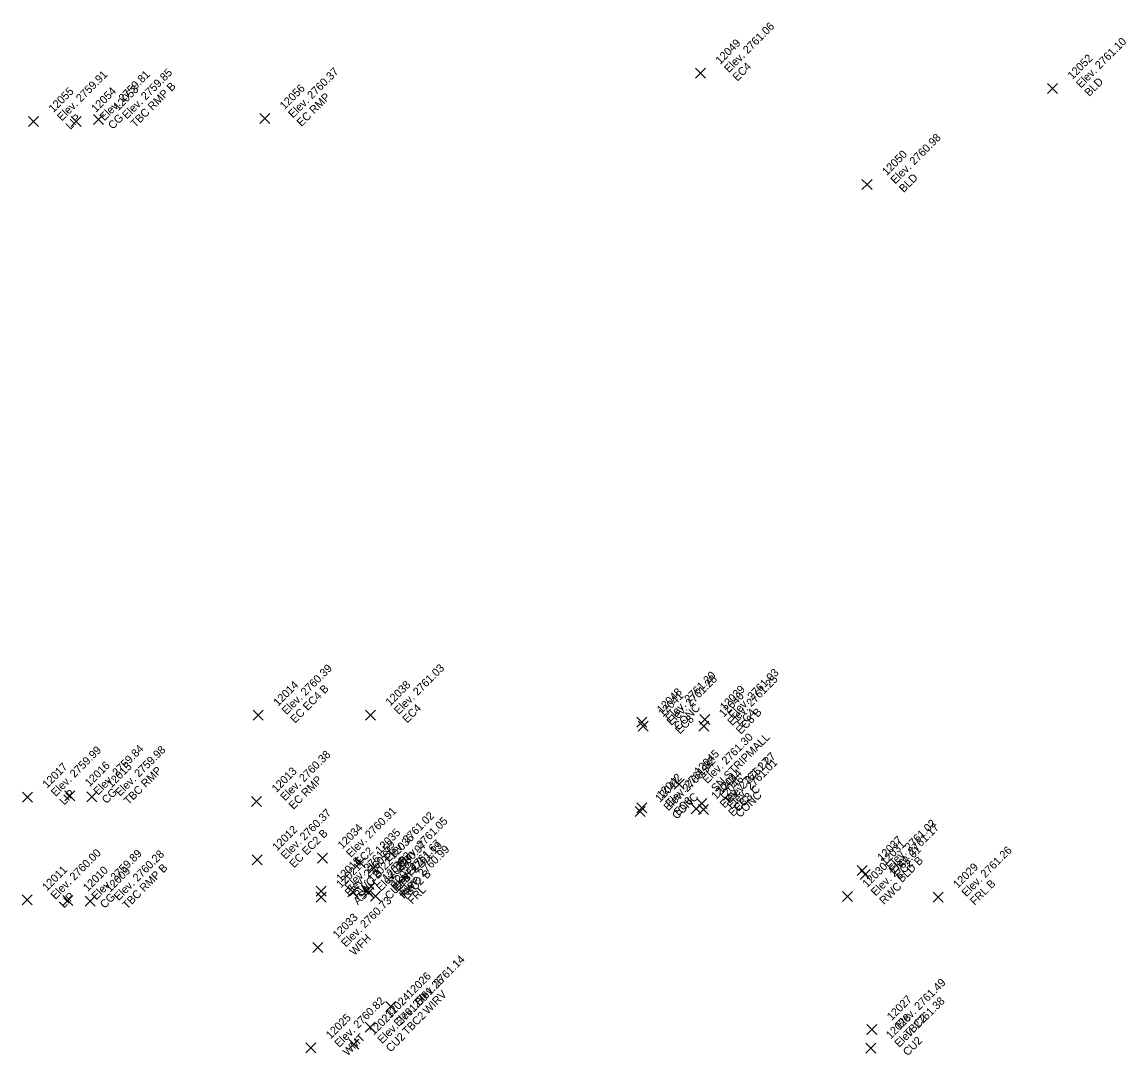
# Model space of a CAD drawing. Extents: x 2493999 to 2503109, y 700767 to 706646.
# Drawn here: x 2502310.86 to 2502343.96, y 702162.62 to 702193.6 of the extents above; entities that cross this region are included whole.
import ezdxf

# ---------------------------------------------------------------- set-up
doc = ezdxf.new("R2010")
doc.units = 0
doc.layers.add('ALG_CL_BLUE_Horiz', color=7, linetype='Continuous')
doc.layers.add('DES_SURFACE_Existing-Ground', color=7, linetype='Continuous')

msp = doc.modelspace()

# ---------------------------------------------------------------- linework, layer by layer
at = {"layer": 'ALG_CL_BLUE_Horiz'}
for points in [[(2502331.202, 702192.065), (2502331.052, 702192.215), (2502331.202, 702192.065), (2502331.052, 702191.915), (2502331.202, 702192.065), (2502331.352, 702191.915), (2502331.202, 702192.065), (2502331.352, 702192.215)], [(2502341.758, 702191.608), (2502341.608, 702191.758), (2502341.758, 702191.608), (2502341.608, 702191.458), (2502341.758, 702191.608), (2502341.908, 702191.458), (2502341.758, 702191.608), (2502341.908, 702191.758)], [(2502311.202, 702190.617), (2502311.052, 702190.767), (2502311.202, 702190.617), (2502311.052, 702190.467), (2502311.202, 702190.617), (2502311.352, 702190.467), (2502311.202, 702190.617), (2502311.352, 702190.767)], [(2502312.478, 702190.622), (2502312.328, 702190.772), (2502312.478, 702190.622), (2502312.328, 702190.472), (2502312.478, 702190.622), (2502312.628, 702190.472), (2502312.478, 702190.622), (2502312.628, 702190.772)], [(2502313.149, 702190.676), (2502312.999, 702190.826), (2502313.149, 702190.676), (2502312.999, 702190.526), (2502313.149, 702190.676), (2502313.299, 702190.526), (2502313.149, 702190.676), (2502313.299, 702190.826)], [(2502318.135, 702190.706), (2502317.985, 702190.856), (2502318.135, 702190.706), (2502317.985, 702190.556), (2502318.135, 702190.706), (2502318.285, 702190.556), (2502318.135, 702190.706), (2502318.285, 702190.856)], [(2502336.196, 702188.728), (2502336.046, 702188.878), (2502336.196, 702188.728), (2502336.046, 702188.578), (2502336.196, 702188.728), (2502336.346, 702188.578), (2502336.196, 702188.728), (2502336.346, 702188.878)], [(2502317.94, 702172.81), (2502317.79, 702172.96), (2502317.94, 702172.81), (2502317.79, 702172.66), (2502317.94, 702172.81), (2502318.09, 702172.66), (2502317.94, 702172.81), (2502318.09, 702172.96)], [(2502321.305, 702172.818), (2502321.155, 702172.968), (2502321.305, 702172.818), (2502321.155, 702172.668), (2502321.305, 702172.818), (2502321.455, 702172.668), (2502321.305, 702172.818), (2502321.455, 702172.968)], [(2502331.334, 702172.68), (2502331.184, 702172.83), (2502331.334, 702172.68), (2502331.184, 702172.53), (2502331.334, 702172.68), (2502331.484, 702172.53), (2502331.334, 702172.68), (2502331.484, 702172.83)], [(2502329.443, 702172.6), (2502329.293, 702172.75), (2502329.443, 702172.6), (2502329.293, 702172.45), (2502329.443, 702172.6), (2502329.593, 702172.45), (2502329.443, 702172.6), (2502329.593, 702172.75)], [(2502329.483, 702172.487), (2502329.333, 702172.637), (2502329.483, 702172.487), (2502329.333, 702172.337), (2502329.483, 702172.487), (2502329.633, 702172.337), (2502329.483, 702172.487), (2502329.633, 702172.637)], [(2502331.304, 702172.484), (2502331.154, 702172.634), (2502331.304, 702172.484), (2502331.154, 702172.334), (2502331.304, 702172.484), (2502331.454, 702172.334), (2502331.304, 702172.484), (2502331.454, 702172.634)], [(2502330.561, 702170.747), (2502330.411, 702170.897), (2502330.561, 702170.747), (2502330.411, 702170.597), (2502330.561, 702170.747), (2502330.711, 702170.597), (2502330.561, 702170.747), (2502330.711, 702170.897)], [(2502311.017, 702170.355), (2502310.867, 702170.505), (2502311.017, 702170.355), (2502310.867, 702170.205), (2502311.017, 702170.355), (2502311.167, 702170.205), (2502311.017, 702170.355), (2502311.167, 702170.505)], [(2502312.289, 702170.397), (2502312.139, 702170.547), (2502312.289, 702170.397), (2502312.139, 702170.247), (2502312.289, 702170.397), (2502312.439, 702170.247), (2502312.289, 702170.397), (2502312.439, 702170.547)], [(2502312.947, 702170.365), (2502312.797, 702170.515), (2502312.947, 702170.365), (2502312.797, 702170.215), (2502312.947, 702170.365), (2502313.097, 702170.215), (2502312.947, 702170.365), (2502313.097, 702170.515)], [(2502317.892, 702170.226), (2502317.742, 702170.376), (2502317.892, 702170.226), (2502317.742, 702170.076), (2502317.892, 702170.226), (2502318.042, 702170.076), (2502317.892, 702170.226), (2502318.042, 702170.376)], [(2502329.439, 702170.037), (2502329.289, 702170.187), (2502329.439, 702170.037), (2502329.289, 702169.887), (2502329.439, 702170.037), (2502329.589, 702169.887), (2502329.439, 702170.037), (2502329.589, 702170.187)], [(2502331.243, 702170.166), (2502331.093, 702170.316), (2502331.243, 702170.166), (2502331.093, 702170.016), (2502331.243, 702170.166), (2502331.393, 702170.016), (2502331.243, 702170.166), (2502331.393, 702170.316)], [(2502329.39, 702169.93), (2502329.24, 702170.08), (2502329.39, 702169.93), (2502329.24, 702169.78), (2502329.39, 702169.93), (2502329.54, 702169.78), (2502329.39, 702169.93), (2502329.54, 702170.08)], [(2502331.076, 702170.009), (2502330.926, 702170.159), (2502331.076, 702170.009), (2502330.926, 702169.859), (2502331.076, 702170.009), (2502331.226, 702169.859), (2502331.076, 702170.009), (2502331.226, 702170.159)], [(2502331.29, 702169.981), (2502331.14, 702170.131), (2502331.29, 702169.981), (2502331.14, 702169.831), (2502331.29, 702169.981), (2502331.44, 702169.831), (2502331.29, 702169.981), (2502331.44, 702170.131)], [(2502317.911, 702168.472), (2502317.761, 702168.622), (2502317.911, 702168.472), (2502317.761, 702168.322), (2502317.911, 702168.472), (2502318.061, 702168.322), (2502317.911, 702168.472), (2502318.061, 702168.622)], [(2502319.87, 702168.529), (2502319.72, 702168.679), (2502319.87, 702168.529), (2502319.72, 702168.379), (2502319.87, 702168.529), (2502320.02, 702168.379), (2502319.87, 702168.529), (2502320.02, 702168.679)], [(2502321.001, 702168.387), (2502320.851, 702168.537), (2502321.001, 702168.387), (2502320.851, 702168.237), (2502321.001, 702168.387), (2502321.151, 702168.237), (2502321.001, 702168.387), (2502321.151, 702168.537)], [(2502321.407, 702168.23), (2502321.257, 702168.38), (2502321.407, 702168.23), (2502321.257, 702168.08), (2502321.407, 702168.23), (2502321.557, 702168.08), (2502321.407, 702168.23), (2502321.557, 702168.38)], [(2502336.054, 702168.16), (2502335.904, 702168.31), (2502336.054, 702168.16), (2502335.904, 702168.01), (2502336.054, 702168.16), (2502336.204, 702168.01), (2502336.054, 702168.16), (2502336.204, 702168.31)], [(2502336.142, 702168.034), (2502335.992, 702168.184), (2502336.142, 702168.034), (2502335.992, 702167.884), (2502336.142, 702168.034), (2502336.292, 702167.884), (2502336.142, 702168.034), (2502336.292, 702168.184)], [(2502319.825, 702167.538), (2502319.675, 702167.688), (2502319.825, 702167.538), (2502319.675, 702167.388), (2502319.825, 702167.538), (2502319.975, 702167.388), (2502319.825, 702167.538), (2502319.975, 702167.688)], [(2502320.775, 702167.518), (2502320.625, 702167.668), (2502320.775, 702167.518), (2502320.625, 702167.368), (2502320.775, 702167.518), (2502320.925, 702167.368), (2502320.775, 702167.518), (2502320.925, 702167.668)], [(2502321.205, 702167.552), (2502321.055, 702167.702), (2502321.205, 702167.552), (2502321.055, 702167.402), (2502321.205, 702167.552), (2502321.355, 702167.402), (2502321.205, 702167.552), (2502321.355, 702167.702)], [(2502321.245, 702167.498), (2502321.095, 702167.648), (2502321.245, 702167.498), (2502321.095, 702167.348), (2502321.245, 702167.498), (2502321.395, 702167.348), (2502321.245, 702167.498), (2502321.395, 702167.648)], [(2502321.459, 702167.382), (2502321.309, 702167.532), (2502321.459, 702167.382), (2502321.309, 702167.232), (2502321.459, 702167.382), (2502321.609, 702167.232), (2502321.459, 702167.382), (2502321.609, 702167.532)], [(2502335.607, 702167.372), (2502335.457, 702167.522), (2502335.607, 702167.372), (2502335.457, 702167.222), (2502335.607, 702167.372), (2502335.757, 702167.222), (2502335.607, 702167.372), (2502335.757, 702167.522)], [(2502311.009, 702167.272), (2502310.859, 702167.422), (2502311.009, 702167.272), (2502310.859, 702167.122), (2502311.009, 702167.272), (2502311.159, 702167.122), (2502311.009, 702167.272), (2502311.159, 702167.422)], [(2502312.234, 702167.256), (2502312.084, 702167.406), (2502312.234, 702167.256), (2502312.084, 702167.106), (2502312.234, 702167.256), (2502312.384, 702167.106), (2502312.234, 702167.256), (2502312.384, 702167.406)], [(2502312.903, 702167.237), (2502312.753, 702167.387), (2502312.903, 702167.237), (2502312.753, 702167.087), (2502312.903, 702167.237), (2502313.053, 702167.087), (2502312.903, 702167.237), (2502313.053, 702167.387)], [(2502319.83, 702167.359), (2502319.68, 702167.509), (2502319.83, 702167.359), (2502319.68, 702167.209), (2502319.83, 702167.359), (2502319.98, 702167.209), (2502319.83, 702167.359), (2502319.98, 702167.509)], [(2502338.326, 702167.352), (2502338.176, 702167.502), (2502338.326, 702167.352), (2502338.176, 702167.202), (2502338.326, 702167.352), (2502338.476, 702167.202), (2502338.326, 702167.352), (2502338.476, 702167.502)], [(2502319.723, 702165.842), (2502319.573, 702165.992), (2502319.723, 702165.842), (2502319.573, 702165.692), (2502319.723, 702165.842), (2502319.873, 702165.692), (2502319.723, 702165.842), (2502319.873, 702165.992)], [(2502321.919, 702164.08), (2502321.769, 702164.23), (2502321.919, 702164.08), (2502321.769, 702163.93), (2502321.919, 702164.08), (2502322.069, 702163.93), (2502321.919, 702164.08), (2502322.069, 702164.23)], [(2502321.299, 702163.454), (2502321.149, 702163.604), (2502321.299, 702163.454), (2502321.149, 702163.304), (2502321.299, 702163.454), (2502321.449, 702163.304), (2502321.299, 702163.454), (2502321.449, 702163.604)], [(2502336.34, 702163.385), (2502336.19, 702163.535), (2502336.34, 702163.385), (2502336.19, 702163.235), (2502336.34, 702163.385), (2502336.49, 702163.235), (2502336.34, 702163.385), (2502336.49, 702163.535)], [(2502319.518, 702162.833), (2502319.368, 702162.983), (2502319.518, 702162.833), (2502319.368, 702162.683), (2502319.518, 702162.833), (2502319.668, 702162.683), (2502319.518, 702162.833), (2502319.668, 702162.983)], [(2502320.809, 702162.947), (2502320.659, 702163.097), (2502320.809, 702162.947), (2502320.659, 702162.797), (2502320.809, 702162.947), (2502320.959, 702162.797), (2502320.809, 702162.947), (2502320.959, 702163.097)], [(2502336.312, 702162.831), (2502336.162, 702162.981), (2502336.312, 702162.831), (2502336.162, 702162.681), (2502336.312, 702162.831), (2502336.462, 702162.681), (2502336.312, 702162.831), (2502336.462, 702162.981)]]:
    msp.add_lwpolyline(points, dxfattribs=at)

# ---------------------------------------------------------------- texts
at = {"layer": 'DES_SURFACE_Existing-Ground'}
for s, p in [('Elev. 2761.06', (2502332.051, 702192.065)), ('12049', (2502331.796, 702192.32)), ('Elev. 2761.10', (2502342.607, 702191.608)), ('EC4', (2502332.305, 702191.81)), ('12052', (2502342.352, 702191.863)), ('Elev. 2759.91', (2502312.051, 702190.617)), ('Elev. 2759.81', (2502313.327, 702190.622)), ('Elev. 2759.85', (2502313.998, 702190.676)), ('Elev. 2760.37', (2502318.984, 702190.706)), ('12053', (2502313.743, 702190.931)), ('TBC RMP B', (2502314.252, 702190.421)), ('12056', (2502318.729, 702190.961)), ('BLD', (2502342.861, 702191.353)), ('12055', (2502311.796, 702190.872)), ('12054', (2502313.072, 702190.877)), ('EC RMP', (2502319.238, 702190.451)), ('LIP', (2502312.305, 702190.362)), ('CG', (2502313.581, 702190.367)), ('Elev. 2760.98', (2502337.045, 702188.728)), ('12050', (2502336.79, 702188.983)), ('BLD', (2502337.299, 702188.473)), ('Elev. 2760.39', (2502318.789, 702172.81)), ('Elev. 2761.03', (2502322.154, 702172.818)), ('Elev. 2761.03', (2502332.183, 702172.68)), ('12014', (2502318.534, 702173.065)), ('12038', (2502321.899, 702173.073)), ('Elev. 2761.20', (2502330.292, 702172.6)), ('Elev. 2761.28', (2502330.332, 702172.487)), ('Elev. 2761.25', (2502332.153, 702172.484)), ('EC EC4 B', (2502319.043, 702172.555)), ('12048', (2502330.037, 702172.855)), ('12041', (2502330.077, 702172.742)), ('12040', (2502331.898, 702172.739)), ('12039', (2502331.928, 702172.935)), ('EC4', (2502322.408, 702172.563)), ('CONC', (2502330.546, 702172.345)), ('EC8', (2502330.586, 702172.232)), ('EC8 B', (2502332.407, 702172.229)), ('EC4', (2502332.437, 702172.425)), ('Elev. 2761.30', (2502331.41, 702170.747)), ('SN STRIPMALL', (2502331.664, 702170.492)), ('Elev. 2759.99', (2502311.866, 702170.355)), ('Elev. 2759.84', (2502313.138, 702170.397)), ('Elev. 2759.98', (2502313.796, 702170.365)), ('Elev. 2760.38', (2502318.741, 702170.226)), ('Elev. 2761.32', (2502330.288, 702170.037)), ('12045', (2502331.155, 702171.002)), ('Elev. 2761.27', (2502331.925, 702170.009)), ('Elev. 2761.27', (2502332.092, 702170.166)), ('Elev. 2761.01', (2502332.139, 702169.981)), ('12017', (2502311.611, 702170.61)), ('12016', (2502312.883, 702170.652)), ('12015', (2502313.541, 702170.62)), ('TBC RMP', (2502314.05, 702170.11)), ('12013', (2502318.486, 702170.481)), ('Elev. 2760.94', (2502330.239, 702169.93)), ('12044', (2502331.837, 702170.421)), ('EC RMP', (2502318.995, 702169.971)), ('12047', (2502329.984, 702170.185)), ('12042', (2502330.033, 702170.292)), ('12043', (2502331.67, 702170.264)), ('12046', (2502331.884, 702170.236)), ('LIP', (2502312.12, 702170.1)), ('CG', (2502313.392, 702170.142)), ('EC8 C', (2502332.346, 702169.911)), ('CONC', (2502332.393, 702169.726)), ('CONC', (2502330.493, 702169.675)), ('EC8', (2502330.542, 702169.782)), ('EC8', (2502332.179, 702169.754)), ('Elev. 2760.37', (2502318.76, 702168.472)), ('Elev. 2760.91', (2502320.719, 702168.529)), ('Elev. 2761.02', (2502321.85, 702168.387)), ('12034', (2502320.464, 702168.784)), ('Elev. 2761.05', (2502322.256, 702168.23)), ('Elev. 2761.02', (2502336.903, 702168.16)), ('Elev. 2761.17', (2502336.991, 702168.034)), ('12012', (2502318.505, 702168.727)), ('EC EC2 B', (2502319.014, 702168.217)), ('12035', (2502321.595, 702168.642)), ('12036', (2502322.001, 702168.485)), ('12037', (2502336.648, 702168.415)), ('Elev. 2761.59', (2502320.674, 702167.538)), ('Elev. 2760.85', (2502320.679, 702167.359)), ('EC2', (2502320.973, 702168.274)), ('Elev. 2760.97', (2502321.624, 702167.518)), ('Elev. 2761.67', (2502322.054, 702167.552)), ('Elev. 2761.19', (2502322.094, 702167.498)), ('Elev. 2760.99', (2502322.308, 702167.382)), ('Elev. 2762.01', (2502336.456, 702167.372)), ('12031', (2502336.736, 702168.289)), ('Elev. 2761.26', (2502339.175, 702167.352)), ('Elev. 2760.00', (2502311.858, 702167.272)), ('Elev. 2759.89', (2502313.083, 702167.256)), ('Elev. 2760.28', (2502313.752, 702167.237)), ('12018', (2502320.419, 702167.793)), ('12022', (2502321.369, 702167.773)), ('12019', (2502321.799, 702167.807)), ('12020', (2502321.839, 702167.753)), ('EC2', (2502322.104, 702168.132)), ('EC2', (2502322.51, 702167.975)), ('BLD B', (2502337.245, 702167.779)), ('12011', (2502311.603, 702167.527)), ('12010', (2502312.828, 702167.511)), ('12009', (2502313.497, 702167.492)), ('TBC RMP B', (2502314.006, 702166.982)), ('12021', (2502320.424, 702167.614)), ('RWC B', (2502320.928, 702167.283)), ('12032', (2502322.053, 702167.637)), ('TBC2 B', (2502322.348, 702167.243)), ('12030', (2502336.201, 702167.627)), ('EC2', (2502337.157, 702167.905)), ('12029', (2502338.92, 702167.607)), ('ASPH', (2502320.933, 702167.104)), ('CU2 B', (2502321.878, 702167.263)), ('RWC', (2502322.308, 702167.297)), ('FRL B', (2502339.429, 702167.097)), ('FRL', (2502322.562, 702167.127)), ('RWC', (2502336.71, 702167.117)), ('LIP', (2502312.112, 702167.017)), ('CG', (2502313.337, 702167.001)), ('Elev. 2760.73', (2502320.572, 702165.842)), ('12033', (2502320.317, 702166.097)), ('WFH', (2502320.826, 702165.587)), ('Elev. 2761.14', (2502322.768, 702164.08)), ('Elev. 2761.26', (2502322.148, 702163.454)), ('12026', (2502322.513, 702164.335)), ('Elev. 2761.49', (2502337.189, 702163.385)), ('WIRV', (2502323.022, 702163.825)), ('Elev. 2760.82', (2502320.367, 702162.833)), ('Elev. 2761.00', (2502321.658, 702162.947)), ('12024', (2502321.893, 702163.709)), ('12027', (2502336.934, 702163.64)), ('Elev. 2761.38', (2502337.161, 702162.831)), ('12023', (2502321.403, 702163.202)), ('TBC2', (2502322.402, 702163.199)), ('12025', (2502320.112, 702163.088)), ('12028', (2502336.906, 702163.086)), ('TBC2', (2502337.443, 702163.13)), ('WMT', (2502320.621, 702162.578)), ('CU2', (2502321.912, 702162.692)), ('CU2', (2502337.415, 702162.576))]:
    msp.add_text(s, height=0.24, rotation=45, dxfattribs=at).set_placement(p)

doc.saveas('drawing.dxf')
